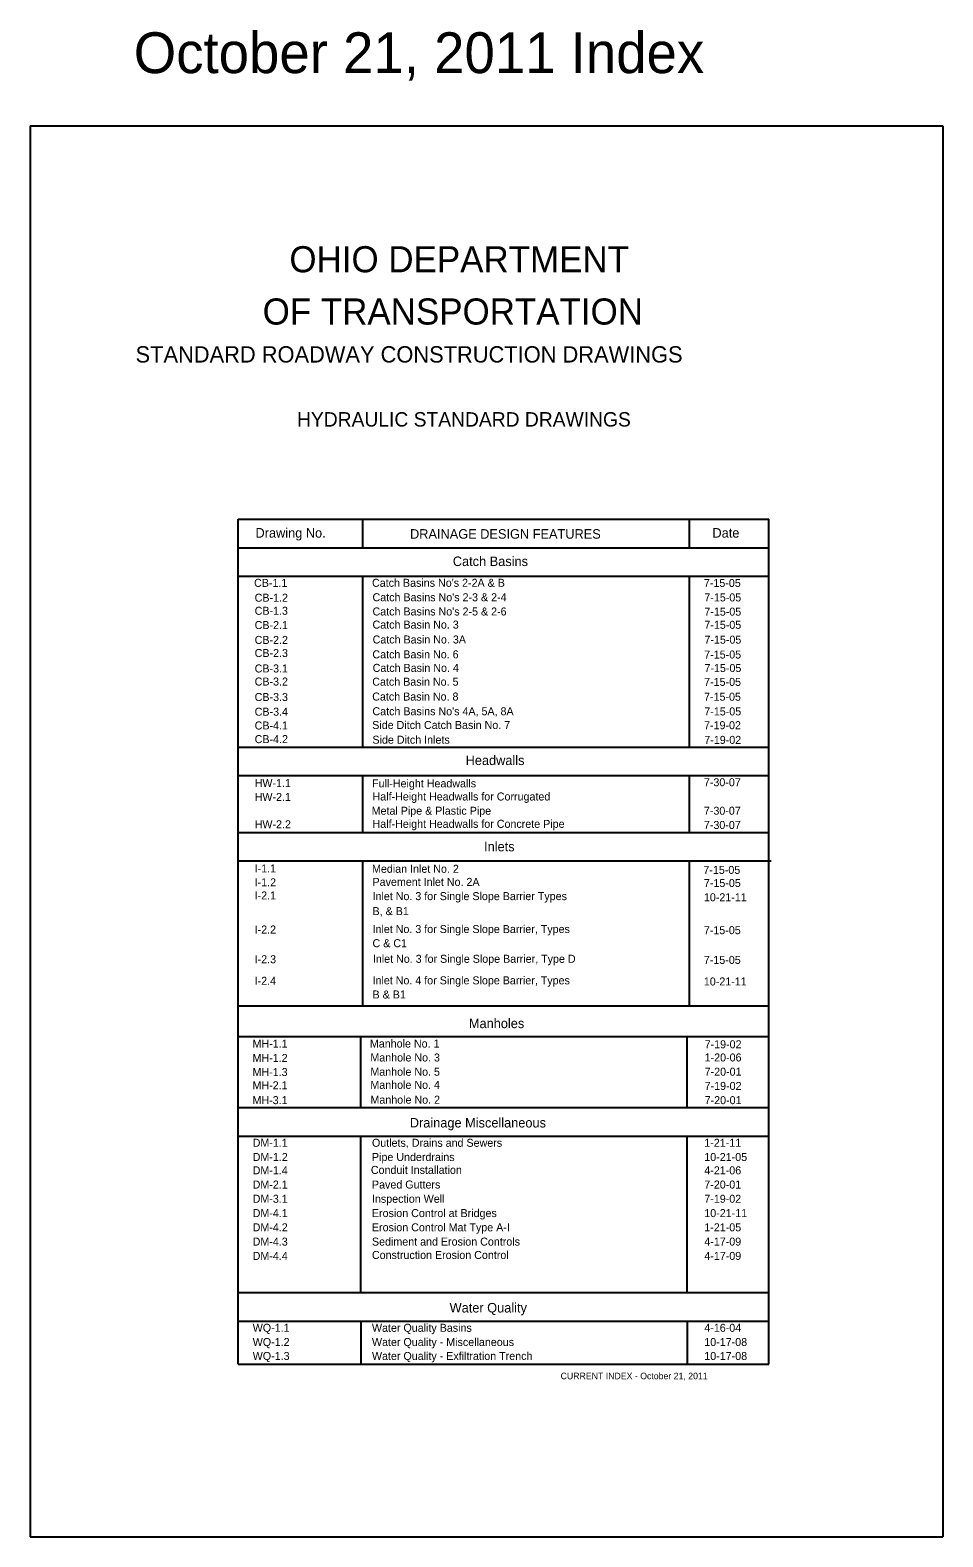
# Model space of a CAD drawing. Extents: x 146 to 619, y 56 to 2134.
# Drawn here: x 597.17 to 619.17, y 2097.9 to 2134.21 of the extents above; entities that cross this region are included whole.
import ezdxf

# ---------------------------------------------------------------- set-up
doc = ezdxf.new("R2010")
doc.units = 0
doc.layers.add('Level 1', color=7, linetype='Continuous')

msp = doc.modelspace()

# ---------------------------------------------------------------- linework, layer by layer
at = {"layer": 'Level 1'}
for p, q in [((597.168, 2131.9), (619.168, 2131.9)), ((597.168, 2131.9), (597.168, 2097.9)), ((619.168, 2131.9), (619.168, 2097.9)), ((602.185, 2102.061), (602.185, 2122.419)), ((602.185, 2122.419), (614.974, 2122.419)), ((602.185, 2122.419), (602.185, 2122.419)), ((605.188, 2121.733), (605.188, 2122.419)), ((613.058, 2121.733), (613.058, 2122.419)), ((614.974, 2102.061), (614.974, 2122.419)), ((614.974, 2122.419), (614.974, 2122.419)), ((602.185, 2121.733), (614.974, 2121.733)), ((602.185, 2121.047), (614.974, 2121.047)), ((605.188, 2116.932), (605.188, 2121.047)), ((613.058, 2116.932), (613.058, 2121.047)), ((602.185, 2116.932), (614.974, 2116.932)), ((602.185, 2116.246), (614.974, 2116.246)), ((605.188, 2114.872), (605.188, 2116.246)), ((613.058, 2114.872), (613.058, 2116.246)), ((602.185, 2114.874), (614.974, 2114.874)), ((602.185, 2114.188), (614.974, 2114.188)), ((602.237, 2114.188), (615.026, 2114.188)), ((605.188, 2114.188), (605.188, 2114.192)), ((605.188, 2110.695), (605.188, 2114.188)), ((613.058, 2114.188), (613.058, 2114.189)), ((613.058, 2110.695), (613.058, 2114.188)), ((602.185, 2110.695), (614.974, 2110.695)), ((602.185, 2109.958), (614.974, 2109.958)), ((605.137, 2108.243), (605.137, 2109.958)), ((613.007, 2108.266), (613.007, 2109.958)), ((605.137, 2108.243), (605.137, 2109.272)), ((613.007, 2108.243), (613.007, 2109.272)), ((602.185, 2108.243), (614.974, 2108.243)), ((602.185, 2107.557), (614.974, 2107.557)), ((605.137, 2106.554), (605.137, 2107.557)), ((613.007, 2106.554), (613.007, 2107.557)), ((613.007, 2105.195), (613.007, 2107.536)), ((605.137, 2104.652), (605.137, 2107.027)), ((605.137, 2103.785), (605.137, 2105.525)), ((613.007, 2103.785), (613.007, 2105.546)), ((602.185, 2103.785), (614.974, 2103.785)), ((602.185, 2103.099), (614.974, 2103.099)), ((605.137, 2103.099), (605.137, 2102.061)), ((613.007, 2103.098), (613.007, 2102.062)), ((602.185, 2102.061), (614.974, 2102.061)), ((597.168, 2097.9), (619.168, 2097.9))]:
    msp.add_line(p, q, dxfattribs=at)

# ---------------------------------------------------------------- texts
for s, height, p in [('October 21, 2011 Index', 0.98375, (599.666, 2133.169)), ('OHIO DEPARTMENT', 0.6296, (603.417, 2128.37)), ('OF TRANSPORTATION', 0.6296, (602.772, 2127.111)), ('STANDARD ROADWAY CONSTRUCTION DRAWINGS', 0.3935, (599.71, 2126.196)), ('HYDRAULIC STANDARD DRAWINGS', 0.34707, (603.601, 2124.653)), ('Drawing No.', 0.23, (602.6, 2121.977)), ('DRAINAGE DESIGN FEATURES', 0.23, (606.325, 2121.951)), ('Date', 0.23, (613.614, 2121.977)), ('Catch Basins', 0.23, (607.356, 2121.292)), ('CB-1.1', 0.1928, (602.566, 2120.791)), ("Catch Basins No's 2-2A & B", 0.1928, (605.409, 2120.792)), ('7-15-05', 0.1928, (613.408, 2120.788)), ('CB-1.2', 0.1928, (602.58, 2120.433)), ("Catch Basins No's 2-3 & 2-4", 0.1928, (605.421, 2120.444)), ('7-15-05', 0.1928, (613.419, 2120.44)), ('CB-1.3', 0.1928, (602.58, 2120.118)), ("Catch Basins No's 2-5 & 2-6", 0.1928, (605.421, 2120.101)), ('7-15-05', 0.1928, (613.419, 2120.097)), ('CB-2.1', 0.1928, (602.58, 2119.774)), ('Catch Basin No. 3', 0.1928, (605.421, 2119.785)), ('7-15-05', 0.1928, (613.419, 2119.78)), ('CB-2.2', 0.1928, (602.58, 2119.416)), ('Catch Basin No. 3A', 0.1928, (605.423, 2119.426)), ('7-15-05', 0.1928, (613.421, 2119.422)), ('CB-2.3', 0.1928, (602.58, 2119.1)), ('Catch Basin No. 6', 0.1928, (605.418, 2119.068)), ('7-15-05', 0.1928, (613.416, 2119.064)), ('CB-3.1', 0.1928, (602.58, 2118.728)), ('Catch Basin No. 4', 0.1928, (605.424, 2118.742)), ('7-15-05', 0.1928, (613.422, 2118.738)), ('CB-3.2', 0.1928, (602.58, 2118.413)), ('Catch Basin No. 5', 0.1928, (605.415, 2118.409)), ('7-15-05', 0.1928, (613.414, 2118.405)), ('CB-3.3', 0.1928, (602.58, 2118.04)), ('Catch Basin No. 8', 0.1928, (605.414, 2118.051)), ('7-15-05', 0.1928, (613.412, 2118.047)), ('CB-3.4', 0.1928, (602.58, 2117.686)), ("Catch Basins No's 4A, 5A, 8A", 0.1928, (605.419, 2117.697)), ('7-15-05', 0.1928, (613.418, 2117.693)), ('CB-4.1', 0.1928, (602.58, 2117.354)), ('Side Ditch Catch Basin No. 7', 0.1928, (605.414, 2117.366)), ('7-19-02', 0.1928, (613.412, 2117.361)), ('CB-4.2', 0.1928, (602.58, 2117.025)), ('Side Ditch Inlets', 0.1928, (605.419, 2117.011)), ('7-19-02', 0.1928, (613.418, 2117.007)), ('Headwalls', 0.23, (607.665, 2116.497)), ('HW-1.1', 0.1928, (602.58, 2115.967)), ('Full-Height Headwalls', 0.1928, (605.409, 2115.959)), ('7-30-07', 0.1928, (613.408, 2115.986)), ('HW-2.1', 0.1928, (602.58, 2115.632)), ('Half-Height Headwalls for Corrugated ', 0.1928, (605.421, 2115.643)), ('       Metal Pipe & Plastic Pipe', 0.1928, (604.898, 2115.3)), ('Half-Height Headwalls for Concrete Pipe', 0.1928, (605.421, 2114.984)), ('7-30-07', 0.1928, (613.408, 2115.3)), ('HW-2.2', 0.1928, (602.58, 2114.974)), ('7-30-07', 0.1928, (613.408, 2114.957)), ('Inlets', 0.23, (608.11, 2114.418)), ('I-1.1', 0.1928, (602.58, 2113.91)), ('Median Inlet No. 2', 0.1928, (605.409, 2113.901)), ('I-1.2', 0.1928, (602.58, 2113.574)), ('Pavement Inlet No. 2A', 0.1928, (605.421, 2113.585)), ('7-15-05', 0.1928, (613.396, 2113.874)), ('7-15-05', 0.1928, (613.408, 2113.558)), ('I-2.1', 0.1928, (602.58, 2113.259)), ('Inlet No. 3 for Single Slope Barrier Types ', 0.1928, (605.421, 2113.242)), ('10-21-11', 0.1928, (613.408, 2113.215)), ('B, & B1', 0.1928, (605.421, 2112.881)), ('I-2.2', 0.1928, (602.58, 2112.438)), ('Inlet No. 3 for Single Slope Barrier, Types', 0.1928, (605.421, 2112.449)), ('C & C1', 0.1928, (605.421, 2112.108)), ('7-15-05', 0.1928, (613.407, 2112.422)), ('I-2.3', 0.1928, (602.58, 2111.721)), ('Inlet No. 3 for Single Slope Barrier, Type D', 0.1928, (605.429, 2111.732)), ('7-15-05', 0.1928, (613.407, 2111.705)), ('I-2.4', 0.1928, (602.58, 2111.202)), ('Inlet No. 4 for Single Slope Barrier, Types', 0.1928, (605.421, 2111.213)), ('10-21-11', 0.1928, (613.407, 2111.186)), ('B & B1', 0.1928, (605.421, 2110.872)), ('Manholes', 0.23, (607.744, 2110.158)), ('MH-1.1', 0.1928, (602.528, 2109.687)), ('Manhole No. 1', 0.1928, (605.358, 2109.69)), ('7-19-02', 0.1928, (613.426, 2109.672)), ('MH-1.2', 0.1928, (602.528, 2109.343)), ('Manhole No. 3', 0.1928, (605.369, 2109.354)), ('1-20-06', 0.1928, (613.426, 2109.355)), ('MH-1.3', 0.1928, (602.528, 2109.003)), ('Manhole No. 5', 0.1928, (605.369, 2109.011)), ('7-20-01', 0.1928, (613.426, 2109.012)), ('MH-2.1', 0.1928, (602.528, 2108.684)), ('Manhole No. 4', 0.1928, (605.369, 2108.695)), ('7-19-02', 0.1928, (613.426, 2108.669)), ('MH-3.1', 0.1928, (602.528, 2108.326)), ('Manhole No. 2', 0.1928, (605.371, 2108.337)), ('7-20-01', 0.1928, (613.426, 2108.326)), ('Drainage Miscellaneous', 0.23, (606.319, 2107.764)), ('DM-1.1', 0.1928, (602.532, 2107.299)), ('Outlets, Drains and Sewers', 0.1928, (605.407, 2107.299)), ('1-21-11', 0.1928, (613.418, 2107.299)), ('DM-1.2', 0.1928, (602.532, 2106.956)), ('DM-1.4', 0.1928, (602.532, 2106.635)), ('Conduit Installation', 0.1928, (605.381, 2106.645)), ('Pipe Underdrains', 0.1928, (605.407, 2106.956)), ('4-21-06', 0.1928, (613.418, 2106.635)), ('10-21-05', 0.1928, (613.418, 2106.956)), ('7-19-02', 0.1928, (613.418, 2105.95)), ('10-21-11', 0.1928, (613.418, 2105.605)), ('1-21-05', 0.1928, (613.418, 2105.262)), ('4-17-09', 0.1928, (613.418, 2104.918)), ('4-17-09', 0.1928, (613.418, 2104.573)), ('Water Quality', 0.23, (607.279, 2103.306)), ('WQ-1.1', 0.1928, (602.533, 2102.841)), ('Water Quality Basins', 0.1928, (605.407, 2102.841)), ('4-16-04', 0.1928, (613.418, 2102.841)), ('WQ-1.2', 0.1928, (602.533, 2102.498)), ('Water Quality - Miscellaneous', 0.1928, (605.407, 2102.498)), ('10-17-08', 0.1928, (613.418, 2102.498)), ('WQ-1.3', 0.1928, (602.533, 2102.162)), ('Water Quality - Exfiltration Trench', 0.1928, (605.407, 2102.162)), ('10-17-08', 0.1928, (613.418, 2102.162)), ('CURRENT INDEX - October 21, 2011', 0.1574, (609.955, 2101.698))]:
    msp.add_text(s, height=height, dxfattribs=at).set_placement(p)
for s, p in [('DM-2.1', (602.532, 2106.293)), ('Paved Gutters', (605.407, 2106.293)), ('7-20-01', (613.418, 2106.293)), ('DM-3.1', (602.532, 2105.95)), ('Inspection Well', (605.407, 2105.95)), ('DM-4.1', (602.532, 2105.605)), ('Erosion Control at Bridges', (605.407, 2105.605)), ('DM-4.2', (602.532, 2105.262)), ('Erosion Control Mat Type A-I', (605.407, 2105.262)), ('DM-4.3', (602.532, 2104.918)), ('Sediment and Erosion Controls', (605.407, 2104.918)), ('DM-4.4', (602.532, 2104.573)), ('Construction Erosion Control', (605.407, 2104.596))]:
    msp.add_text(s, height=0.1928, rotation=360, dxfattribs=at).set_placement(p)

doc.saveas('drawing.dxf')
